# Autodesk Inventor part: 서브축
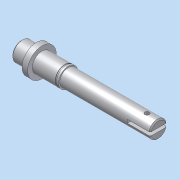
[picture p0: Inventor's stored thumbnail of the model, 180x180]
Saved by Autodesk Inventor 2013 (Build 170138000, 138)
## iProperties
Company: 한국ATC센터
Created: 2014-12
Part Number: 서브축
Document SubType Name: Modeling
Designer: KYOUNG IL JANG
Density: 1 g/cm^3
Mass: 23.2871 g
Surface Area: 76.512 cm^2
Volume: 23.2871 cm^3
Material: 일반
Author: KYOUNG IL JANG
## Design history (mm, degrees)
sketch "스케치1"
  geometry: L1 (0, 0)-(120, 0); L2 (0, 0)-(0, 7.5); L3 (1, 8.5)-(13, 8.5); L4 (13, 8.5)-(13, 12.5); L5 (13, 12.5)-(18, 12.5); L6 (18, 12.5)-(18, 8.5); L7 (18, 8.5)-(41, 8.5); L8 (120, 7.5)-(120, 0); L9 (0, 7.5)-(1, 8.5); L10 (41, 8.5)-(41, 7.5); L11 (41, 7.5)-(120, 7.5); 1 further point
  constraints: 22 end point, 3 parallel, 3 perpendicular, 2 collinear, 2 point on line, 2 vertical, 1 horizontal
  dimensions: "d0" = 5 distance of L4.end L5.end; "d1" = 17 diameter of L7 L1; "d2" = 13 distance of point (0, 8.5) L3.end; "d3" = 25 diameter of L5 L1; "d4" = 120 distance of L1.start L1.end; "d5" = 1 distance of L2.end point (0, 8.5); "d6" = 1 distance of L3.start point (0, 8.5) (= d5); "d15" = 15 diameter of L11 L1; "d16" = 23 distance of L6.end L7.end
revolve "회전1" sketch "스케치1" stored, may be unused: angle "d9" = 90 deg
node "작업 평면1"
sketch "스케치2"
  geometry: L1 (11.5, 12.5)-(11.5, -12.5) reference; L2 (-3, 2.5)-(6, 2.5); L3 (6, -2.5)-(-3, -2.5); A1 r 2.5 centre (6, 0) between (6, -2.5) and (6, 2.5); A2 r 2.5 centre (-3, 0) between (-3, 2.5) and (-3, -2.5); 1 further point
  constraints: 4 end point, 4 point on circle, 4 tangent, 2 centre point, 1 horizontal alignment, 1 parallel, 1 perpendicular
  dimensions: "d10" = 5 distance between parallel lines of L3 L2; "d11" = 14 dimension on A1 A2; "d12" = 3 distance edge to line of A1 L1
extrude "돌출1" cut sketch "스케치2" distance "d13" = 3; taper "d14" = 0 deg
sketch "스케치3"
  geometry: L1 (18, -12.5)-(18, 12.5) reference; L2 (13, -12.5)-(13, 12.5) reference; L3 (18, 8.5)-(41, 8.5) reference; L4 (38, 8.5)-(39.15, 8.5); L5 (39.15, 8.5)-(39.15, 8.1); L6 (39.15, 8.1)-(38, 8.1); L7 (38, 8.1)-(38, 8.5); L8 (-24, 0)-(144, 0) reference; 1 further point
  constraints: 8 end point, 2 parallel, 1 horizontal, 1 perpendicular, 1 point on line
  dimensions: "d17" = 20 distance between parallel lines of L7 L1; "d18" = 1.15 distance of L5.end L6.end; "d19" = 8.1 distance between parallel lines of L6 L8
revolve "회전2" sketch "스케치3" stored, may be unused: angle "d20" = 90 deg
chamfer "모따기1" distance "d21" = 1; stored, may be unused: second distance "d22" = 2, angle "d23" = 45 deg
sketch "스케치4"
  geometry: L1 (-120, 1.5)-(-100, 1.5); L2 (-100, 1.5)-(-100, -1.5); L3 (-100, -1.5)-(-120, -1.5); L4 (-120, -1.5)-(-120, 1.5); L5 (-120, -6.5)-(-120, 6.5) reference; 2 further points
  constraints: 8 end point, 2 parallel, 1 collinear, 1 horizontal, 1 horizontal alignment, 1 midpoint, 1 perpendicular
  dimensions: "d24" = 3 distance between parallel lines of L3 L1; "d25" = 20 distance of L2.end L3.end
extrude "돌출2" cut sketch "스케치4" stored distance "d26" = 10; taper "d27" = 0 deg
sketch "스케치5"
  geometry: L1 (120, 6.325)-(120, -6.325) reference; C1 r 2 at (110, 0); 1 further point
  constraints: 1 centre point, 1 horizontal alignment
  dimensions: "d28" = 4 diameter of C1; "d29" = 10 distance from line of L1 C1.centre
extrude "돌출3" cut sketch "스케치5" stored distance "d30" = 10; taper "d31" = 0 deg
node "솔리드1"
node "투영된 루프1"
